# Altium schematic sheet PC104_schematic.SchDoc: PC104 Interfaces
size A2; DocumentNumber: 3; SheetNumber: 3; SheetTotal: 8
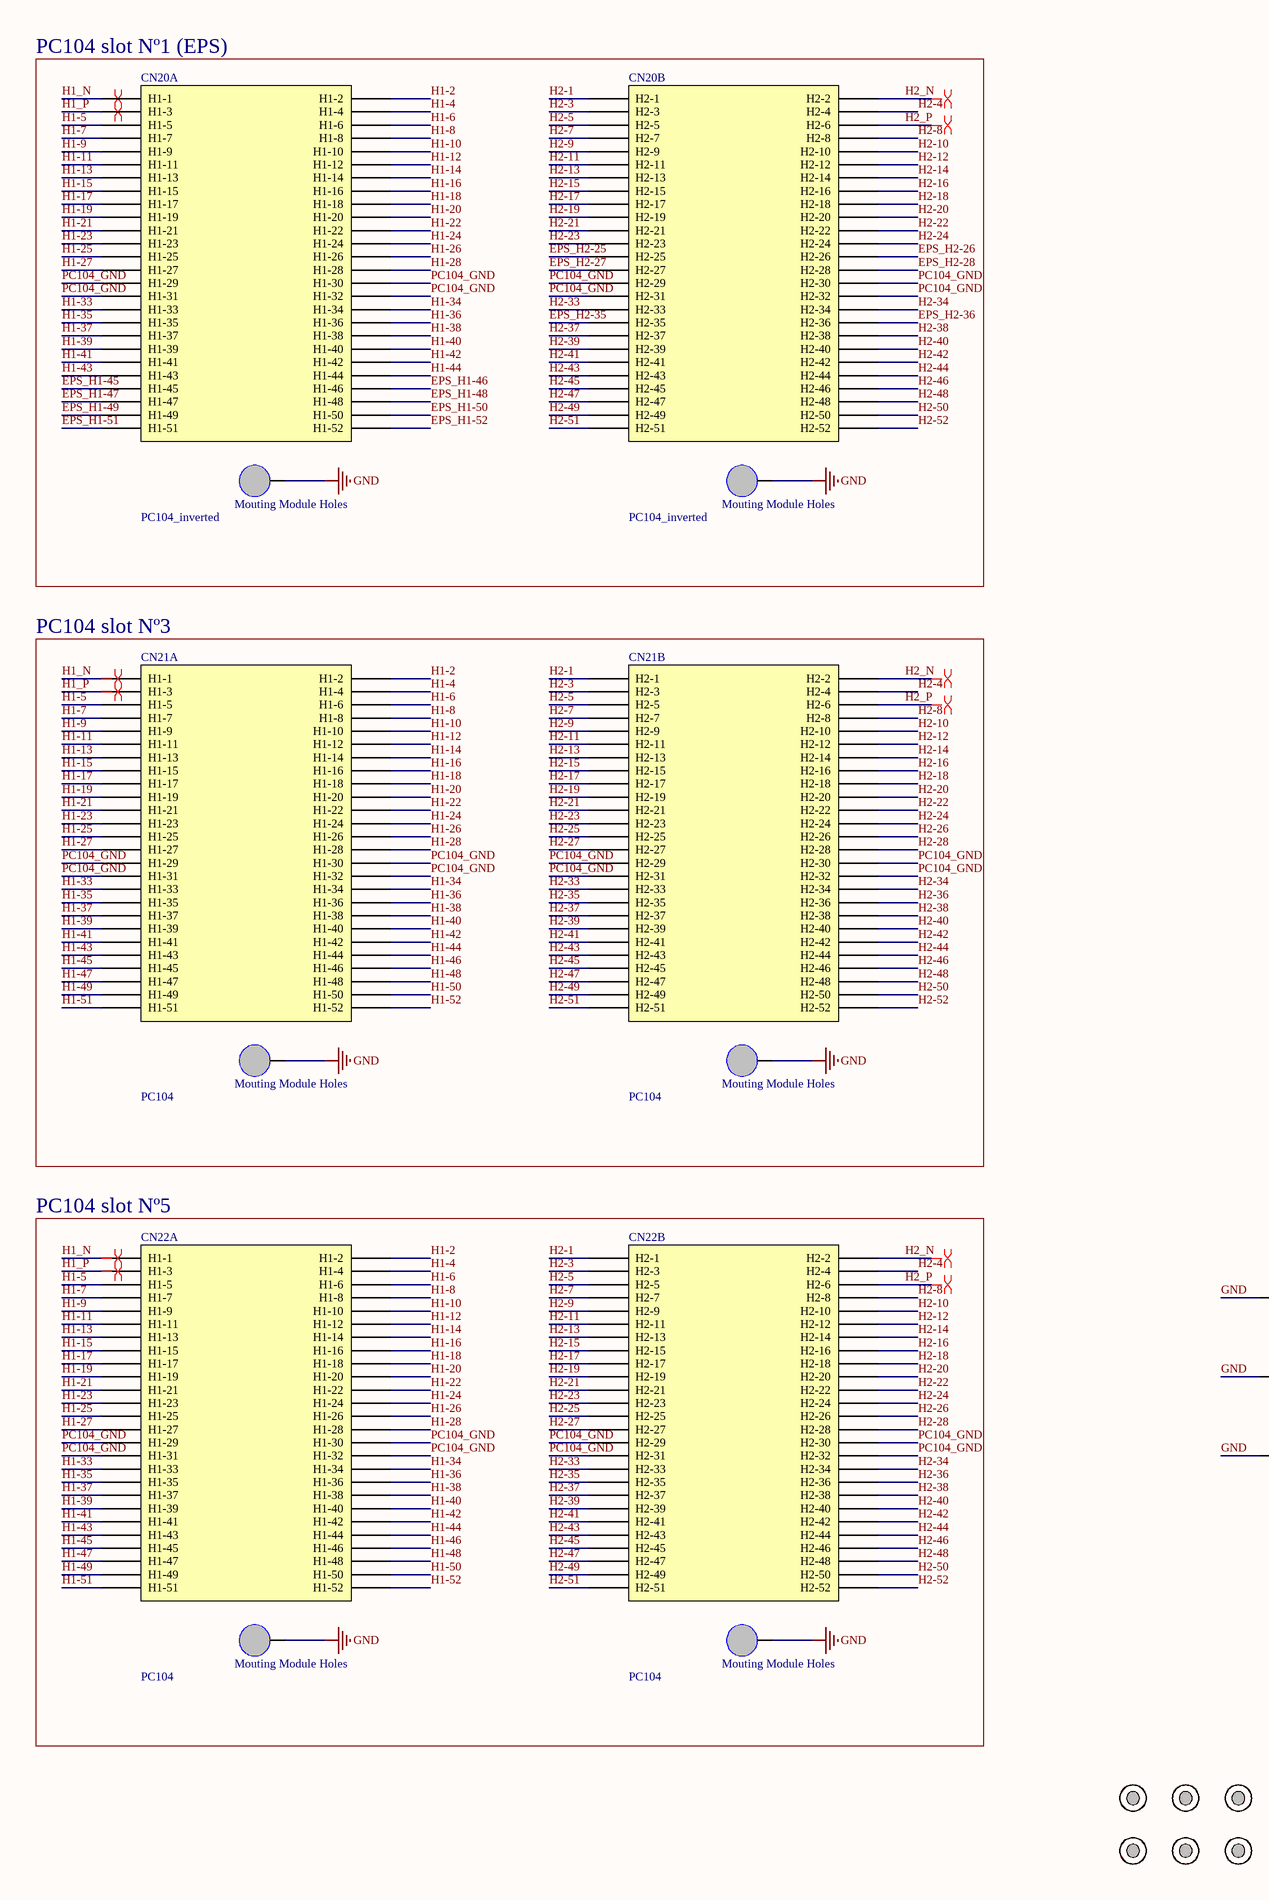
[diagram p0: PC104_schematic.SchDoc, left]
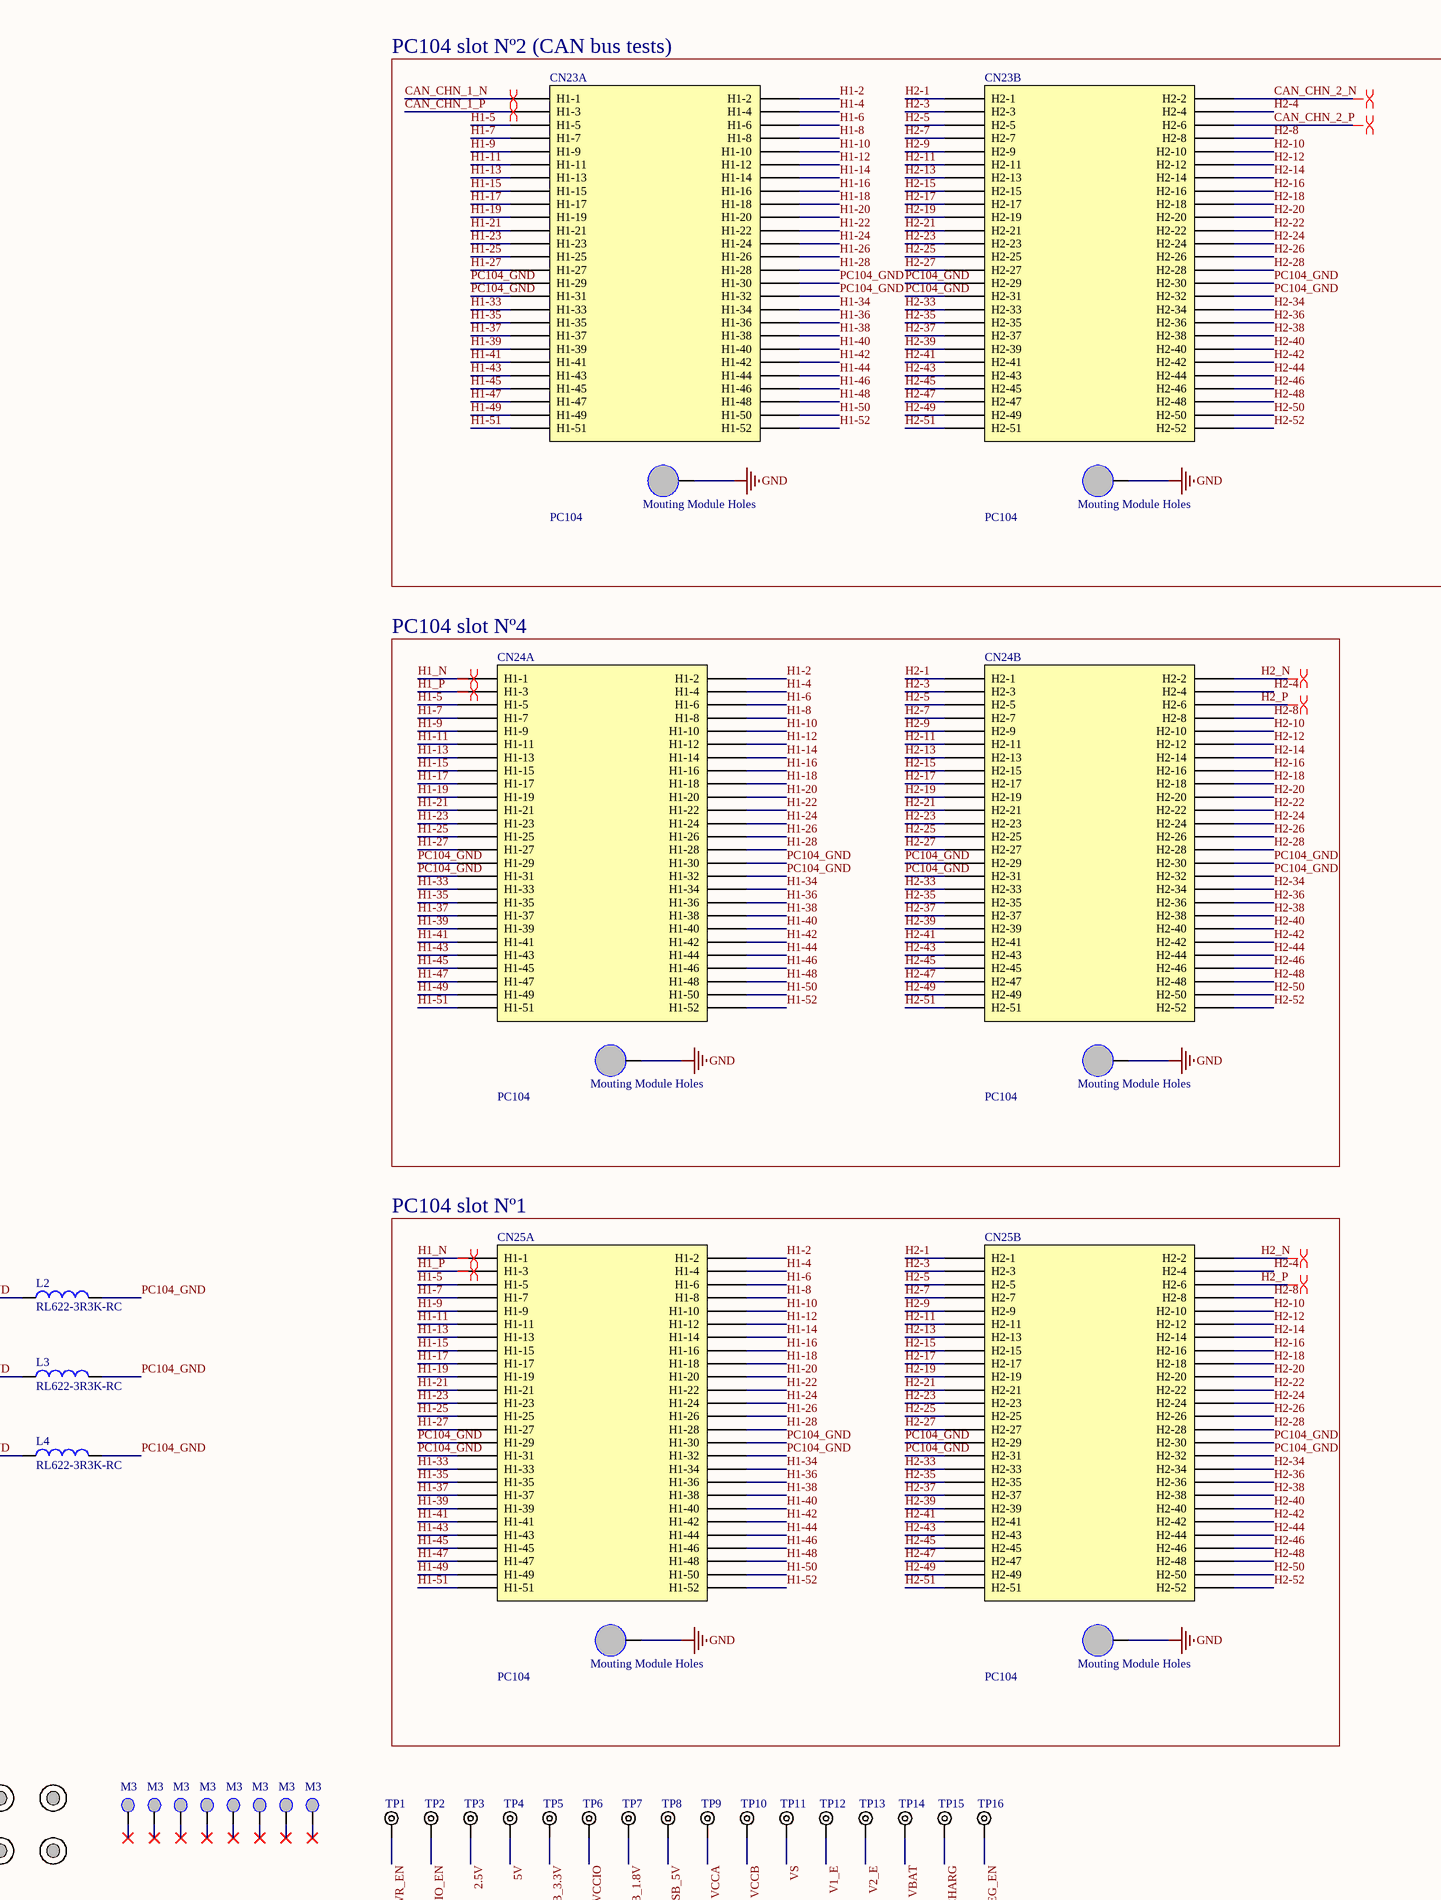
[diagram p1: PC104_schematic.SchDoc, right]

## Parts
CN20  PC104_inverted  [PC104_inverted]  (parts A,B of 2)
CN21  PC104  [PC104]  (parts A,B of 2)
CN22  PC104  [PC104]  (parts A,B of 2)
CN23  PC104  [PC104]  (parts A,B of 2)
CN24  PC104  [PC104]  (parts A,B of 2)
CN25  PC104  [PC104]  (parts A,B of 2)
FD1  Fiducial 1.3  [Fiducial 1.3mm]  (value not drawn)  (no BOM)
FD2  Fiducial 1.3  [Fiducial 1.3mm]  (value not drawn)  (no BOM)
FD3  Fiducial 1.3  [Fiducial 1.3mm]  (value not drawn)  (no BOM)
FD4  Fiducial 1.3  [Fiducial 1.3mm]  (value not drawn)  (no BOM)
FD5  Fiducial 1.3  [Fiducial 1.3mm]  (value not drawn)  (no BOM)
FD6  Fiducial 1.3  [Fiducial 1.3mm]  (value not drawn)  (no BOM)
FD7  Fiducial 1.3  [Fiducial 1.3mm]  (value not drawn)  (no BOM)
FD8  Fiducial 1.3  [Fiducial 1.3mm]  (value not drawn)  (no BOM)
L2  RL622-3R3K-RC  [RL622]
L3  RL622-3R3K-RC  [RL622]
L4  RL622-3R3K-RC  [RL622]
MEC1  M3  [M3 hole]  (no BOM)
MEC2  M3  [M3 hole]  (no BOM)
MEC3  M3  [M3 hole]  (no BOM)
MEC4  M3  [M3 hole]  (no BOM)
MEC5  M3  [M3 hole]  (no BOM)
MEC6  M3  [M3 hole]  (no BOM)
MEC7  M3  [M3 hole]  (no BOM)
MEC8  M3  [M3 hole]  (no BOM)
TP1  (no value)  [TEST POINT PTH]  (no BOM)
TP2  (no value)  [TEST POINT PTH]  (no BOM)
TP3  (no value)  [TEST POINT PTH]  (no BOM)
TP4  (no value)  [TEST POINT PTH]  (no BOM)
TP5  (no value)  [TEST POINT PTH]  (no BOM)
TP6  (no value)  [TEST POINT PTH]  (no BOM)
TP7  (no value)  [TEST POINT PTH]  (no BOM)
TP8  (no value)  [TEST POINT PTH]  (no BOM)
TP9  (no value)  [TEST POINT PTH]  (no BOM)
TP10  (no value)  [TEST POINT PTH]  (no BOM)
TP11  (no value)  [TEST POINT PTH]  (no BOM)
TP12  (no value)  [TEST POINT PTH]  (no BOM)
TP13  (no value)  [TEST POINT PTH]  (no BOM)
TP14  (no value)  [TEST POINT PTH]  (no BOM)
TP15  (no value)  [TEST POINT PTH]  (no BOM)
TP16  (no value)  [TEST POINT PTH]  (no BOM)

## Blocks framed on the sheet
PC104 slot Nº1 (EPS): CN20
PC104 slot Nº2 (CAN bus tests): CN23
PC104 slot Nº3: CN21
PC104 slot Nº4: CN24
PC104 slot Nº5: CN22
PC104 slot Nº1: CN25

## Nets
GND: CN20.0(Mouting) CN21.0(Mouting) CN22.0(Mouting) CN23.0(Mouting) CN24.0(Mouting) CN25.0(Mouting) L2.1 L3.1 L4.1
2.5V: TP3.1
5V: TP4.1
CAN_CHN_1_N: CN23.1(H1-1)
CAN_CHN_1_P: CN23.3(H1-3)
CAN_CHN_2_N: CN23.54(H2-2)
CAN_CHN_2_P: CN23.58(H2-6)
EPS_H1-45: CN20.45(H1-45)
EPS_H1-46: CN20.46(H1-46)
EPS_H1-47: CN20.47(H1-47)
EPS_H1-48: CN20.48(H1-48)
EPS_H1-49: CN20.49(H1-49)
EPS_H1-50: CN20.50(H1-50)
EPS_H1-51: CN20.51(H1-51)
EPS_H1-52: CN20.52(H1-52)
EPS_H2-25: CN20.77(H2-25)
EPS_H2-26: CN20.78(H2-26)
EPS_H2-27: CN20.79(H2-27)
EPS_H2-28: CN20.80(H2-28)
EPS_H2-35: CN20.87(H2-35)
EPS_H2-36: CN20.88(H2-36)
H1-2: CN20.2(H1-2) CN21.2(H1-2) CN22.2(H1-2) CN23.2(H1-2) CN24.2(H1-2) CN25.2(H1-2)
H1-4: CN20.4(H1-4) CN21.4(H1-4) CN22.4(H1-4) CN23.4(H1-4) CN24.4(H1-4) CN25.4(H1-4)
H1-5: CN20.5(H1-5) CN21.5(H1-5) CN22.5(H1-5) CN23.5(H1-5) CN24.5(H1-5) CN25.5(H1-5)
H1-6: CN20.6(H1-6) CN21.6(H1-6) CN22.6(H1-6) CN23.6(H1-6) CN24.6(H1-6) CN25.6(H1-6)
H1-7: CN20.7(H1-7) CN21.7(H1-7) CN22.7(H1-7) CN23.7(H1-7) CN24.7(H1-7) CN25.7(H1-7)
H1-8: CN20.8(H1-8) CN21.8(H1-8) CN22.8(H1-8) CN23.8(H1-8) CN24.8(H1-8) CN25.8(H1-8)
H1-9: CN20.9(H1-9) CN21.9(H1-9) CN22.9(H1-9) CN23.9(H1-9) CN24.9(H1-9) CN25.9(H1-9)
H1-10: CN20.10(H1-10) CN21.10(H1-10) CN22.10(H1-10) CN23.10(H1-10) CN24.10(H1-10) CN25.10(H1-10)
H1-11: CN20.11(H1-11) CN21.11(H1-11) CN22.11(H1-11) CN23.11(H1-11) CN24.11(H1-11) CN25.11(H1-11)
H1-12: CN20.12(H1-12) CN21.12(H1-12) CN22.12(H1-12) CN23.12(H1-12) CN24.12(H1-12) CN25.12(H1-12)
H1-13: CN20.13(H1-13) CN21.13(H1-13) CN22.13(H1-13) CN23.13(H1-13) CN24.13(H1-13) CN25.13(H1-13)
H1-14: CN20.14(H1-14) CN21.14(H1-14) CN22.14(H1-14) CN23.14(H1-14) CN24.14(H1-14) CN25.14(H1-14)
H1-15: CN20.15(H1-15) CN21.15(H1-15) CN22.15(H1-15) CN23.15(H1-15) CN24.15(H1-15) CN25.15(H1-15)
H1-16: CN20.16(H1-16) CN21.16(H1-16) CN22.16(H1-16) CN23.16(H1-16) CN24.16(H1-16) CN25.16(H1-16)
H1-17: CN20.17(H1-17) CN21.17(H1-17) CN22.17(H1-17) CN23.17(H1-17) CN24.17(H1-17) CN25.17(H1-17)
H1-18: CN20.18(H1-18) CN21.18(H1-18) CN22.18(H1-18) CN23.18(H1-18) CN24.18(H1-18) CN25.18(H1-18)
H1-19: CN20.19(H1-19) CN21.19(H1-19) CN22.19(H1-19) CN23.19(H1-19) CN24.19(H1-19) CN25.19(H1-19)
H1-20: CN20.20(H1-20) CN21.20(H1-20) CN22.20(H1-20) CN23.20(H1-20) CN24.20(H1-20) CN25.20(H1-20)
H1-21: CN20.21(H1-21) CN21.21(H1-21) CN22.21(H1-21) CN23.21(H1-21) CN24.21(H1-21) CN25.21(H1-21)
H1-22: CN20.22(H1-22) CN21.22(H1-22) CN22.22(H1-22) CN23.22(H1-22) CN24.22(H1-22) CN25.22(H1-22)
H1-23: CN20.23(H1-23) CN21.23(H1-23) CN22.23(H1-23) CN23.23(H1-23) CN24.23(H1-23) CN25.23(H1-23)
H1-24: CN20.24(H1-24) CN21.24(H1-24) CN22.24(H1-24) CN23.24(H1-24) CN24.24(H1-24) CN25.24(H1-24)
H1-25: CN20.25(H1-25) CN21.25(H1-25) CN22.25(H1-25) CN23.25(H1-25) CN24.25(H1-25) CN25.25(H1-25)
H1-26: CN20.26(H1-26) CN21.26(H1-26) CN22.26(H1-26) CN23.26(H1-26) CN24.26(H1-26) CN25.26(H1-26)
H1-27: CN20.27(H1-27) CN21.27(H1-27) CN22.27(H1-27) CN23.27(H1-27) CN24.27(H1-27) CN25.27(H1-27)
H1-28: CN20.28(H1-28) CN21.28(H1-28) CN22.28(H1-28) CN23.28(H1-28) CN24.28(H1-28) CN25.28(H1-28)
H1-33: CN20.33(H1-33) CN21.33(H1-33) CN22.33(H1-33) CN23.33(H1-33) CN24.33(H1-33) CN25.33(H1-33)
H1-34: CN20.34(H1-34) CN21.34(H1-34) CN22.34(H1-34) CN23.34(H1-34) CN24.34(H1-34) CN25.34(H1-34)
H1-35: CN20.35(H1-35) CN21.35(H1-35) CN22.35(H1-35) CN23.35(H1-35) CN24.35(H1-35) CN25.35(H1-35)
H1-36: CN20.36(H1-36) CN21.36(H1-36) CN22.36(H1-36) CN23.36(H1-36) CN24.36(H1-36) CN25.36(H1-36)
H1-37: CN20.37(H1-37) CN21.37(H1-37) CN22.37(H1-37) CN23.37(H1-37) CN24.37(H1-37) CN25.37(H1-37)
H1-38: CN20.38(H1-38) CN21.38(H1-38) CN22.38(H1-38) CN23.38(H1-38) CN24.38(H1-38) CN25.38(H1-38)
H1-39: CN20.39(H1-39) CN21.39(H1-39) CN22.39(H1-39) CN23.39(H1-39) CN24.39(H1-39) CN25.39(H1-39)
H1-40: CN20.40(H1-40) CN21.40(H1-40) CN22.40(H1-40) CN23.40(H1-40) CN24.40(H1-40) CN25.40(H1-40)
H1-41: CN20.41(H1-41) CN21.41(H1-41) CN22.41(H1-41) CN23.41(H1-41) CN24.41(H1-41) CN25.41(H1-41)
H1-42: CN20.42(H1-42) CN21.42(H1-42) CN22.42(H1-42) CN23.42(H1-42) CN24.42(H1-42) CN25.42(H1-42)
H1-43: CN20.43(H1-43) CN21.43(H1-43) CN22.43(H1-43) CN23.43(H1-43) CN24.43(H1-43) CN25.43(H1-43)
H1-44: CN20.44(H1-44) CN21.44(H1-44) CN22.44(H1-44) CN23.44(H1-44) CN24.44(H1-44) CN25.44(H1-44)
H1-45: CN21.45(H1-45) CN22.45(H1-45) CN23.45(H1-45) CN24.45(H1-45) CN25.45(H1-45)
H1-46: CN21.46(H1-46) CN22.46(H1-46) CN23.46(H1-46) CN24.46(H1-46) CN25.46(H1-46)
H1-47: CN21.47(H1-47) CN22.47(H1-47) CN23.47(H1-47) CN24.47(H1-47) CN25.47(H1-47)
H1-48: CN21.48(H1-48) CN22.48(H1-48) CN23.48(H1-48) CN24.48(H1-48) CN25.48(H1-48)
H1-49: CN21.49(H1-49) CN22.49(H1-49) CN23.49(H1-49) CN24.49(H1-49) CN25.49(H1-49)
H1-50: CN21.50(H1-50) CN22.50(H1-50) CN23.50(H1-50) CN24.50(H1-50) CN25.50(H1-50)
H1-51: CN21.51(H1-51) CN22.51(H1-51) CN23.51(H1-51) CN24.51(H1-51) CN25.51(H1-51)
H1-52: CN21.52(H1-52) CN22.52(H1-52) CN23.52(H1-52) CN24.52(H1-52) CN25.52(H1-52)
H1_N: CN20.1(H1-1) CN21.1(H1-1) CN22.1(H1-1) CN24.1(H1-1) CN25.1(H1-1)
H1_P: CN20.3(H1-3) CN21.3(H1-3) CN22.3(H1-3) CN24.3(H1-3) CN25.3(H1-3)
H2-1: CN20.53(H2-1) CN21.53(H2-1) CN22.53(H2-1) CN23.53(H2-1) CN24.53(H2-1) CN25.53(H2-1)
H2-3: CN20.55(H2-3) CN21.55(H2-3) CN22.55(H2-3) CN23.55(H2-3) CN24.55(H2-3) CN25.55(H2-3)
H2-4: CN20.56(H2-4) CN21.56(H2-4) CN22.56(H2-4) CN23.56(H2-4) CN24.56(H2-4) CN25.56(H2-4)
H2-5: CN20.57(H2-5) CN21.57(H2-5) CN22.57(H2-5) CN23.57(H2-5) CN24.57(H2-5) CN25.57(H2-5)
H2-7: CN20.59(H2-7) CN21.59(H2-7) CN22.59(H2-7) CN23.59(H2-7) CN24.59(H2-7) CN25.59(H2-7)
H2-8: CN20.60(H2-8) CN21.60(H2-8) CN22.60(H2-8) CN23.60(H2-8) CN24.60(H2-8) CN25.60(H2-8)
H2-9: CN20.61(H2-9) CN21.61(H2-9) CN22.61(H2-9) CN23.61(H2-9) CN24.61(H2-9) CN25.61(H2-9)
H2-10: CN20.62(H2-10) CN21.62(H2-10) CN22.62(H2-10) CN23.62(H2-10) CN24.62(H2-10) CN25.62(H2-10)
H2-11: CN20.63(H2-11) CN21.63(H2-11) CN22.63(H2-11) CN23.63(H2-11) CN24.63(H2-11) CN25.63(H2-11)
H2-12: CN20.64(H2-12) CN21.64(H2-12) CN22.64(H2-12) CN23.64(H2-12) CN24.64(H2-12) CN25.64(H2-12)
H2-13: CN20.65(H2-13) CN21.65(H2-13) CN22.65(H2-13) CN23.65(H2-13) CN24.65(H2-13) CN25.65(H2-13)
H2-14: CN20.66(H2-14) CN21.66(H2-14) CN22.66(H2-14) CN23.66(H2-14) CN24.66(H2-14) CN25.66(H2-14)
H2-15: CN20.67(H2-15) CN21.67(H2-15) CN22.67(H2-15) CN23.67(H2-15) CN24.67(H2-15) CN25.67(H2-15)
H2-16: CN20.68(H2-16) CN21.68(H2-16) CN22.68(H2-16) CN23.68(H2-16) CN24.68(H2-16) CN25.68(H2-16)
H2-17: CN20.69(H2-17) CN21.69(H2-17) CN22.69(H2-17) CN23.69(H2-17) CN24.69(H2-17) CN25.69(H2-17)
H2-18: CN20.70(H2-18) CN21.70(H2-18) CN22.70(H2-18) CN23.70(H2-18) CN24.70(H2-18) CN25.70(H2-18)
H2-19: CN20.71(H2-19) CN21.71(H2-19) CN22.71(H2-19) CN23.71(H2-19) CN24.71(H2-19) CN25.71(H2-19)
H2-20: CN20.72(H2-20) CN21.72(H2-20) CN22.72(H2-20) CN23.72(H2-20) CN24.72(H2-20) CN25.72(H2-20)
H2-21: CN20.73(H2-21) CN21.73(H2-21) CN22.73(H2-21) CN23.73(H2-21) CN24.73(H2-21) CN25.73(H2-21)
H2-22: CN20.74(H2-22) CN21.74(H2-22) CN22.74(H2-22) CN23.74(H2-22) CN24.74(H2-22) CN25.74(H2-22)
H2-23: CN20.75(H2-23) CN21.75(H2-23) CN22.75(H2-23) CN23.75(H2-23) CN24.75(H2-23) CN25.75(H2-23)
H2-24: CN20.76(H2-24) CN21.76(H2-24) CN22.76(H2-24) CN23.76(H2-24) CN24.76(H2-24) CN25.76(H2-24)
H2-25: CN21.77(H2-25) CN22.77(H2-25) CN23.77(H2-25) CN24.77(H2-25) CN25.77(H2-25)
H2-26: CN21.78(H2-26) CN22.78(H2-26) CN23.78(H2-26) CN24.78(H2-26) CN25.78(H2-26)
H2-27: CN21.79(H2-27) CN22.79(H2-27) CN23.79(H2-27) CN24.79(H2-27) CN25.79(H2-27)
H2-28: CN21.80(H2-28) CN22.80(H2-28) CN23.80(H2-28) CN24.80(H2-28) CN25.80(H2-28)
H2-33: CN20.85(H2-33) CN21.85(H2-33) CN22.85(H2-33) CN23.85(H2-33) CN24.85(H2-33) CN25.85(H2-33)
H2-34: CN20.86(H2-34) CN21.86(H2-34) CN22.86(H2-34) CN23.86(H2-34) CN24.86(H2-34) CN25.86(H2-34)
H2-35: CN21.87(H2-35) CN22.87(H2-35) CN23.87(H2-35) CN24.87(H2-35) CN25.87(H2-35)
H2-36: CN21.88(H2-36) CN22.88(H2-36) CN23.88(H2-36) CN24.88(H2-36) CN25.88(H2-36)
H2-37: CN20.89(H2-37) CN21.89(H2-37) CN22.89(H2-37) CN23.89(H2-37) CN24.89(H2-37) CN25.89(H2-37)
H2-38: CN20.90(H2-38) CN21.90(H2-38) CN22.90(H2-38) CN23.90(H2-38) CN24.90(H2-38) CN25.90(H2-38)
H2-39: CN20.91(H2-39) CN21.91(H2-39) CN22.91(H2-39) CN23.91(H2-39) CN24.91(H2-39) CN25.91(H2-39)
H2-40: CN20.92(H2-40) CN21.92(H2-40) CN22.92(H2-40) CN23.92(H2-40) CN24.92(H2-40) CN25.92(H2-40)
H2-41: CN20.93(H2-41) CN21.93(H2-41) CN22.93(H2-41) CN23.93(H2-41) CN24.93(H2-41) CN25.93(H2-41)
H2-42: CN20.94(H2-42) CN21.94(H2-42) CN22.94(H2-42) CN23.94(H2-42) CN24.94(H2-42) CN25.94(H2-42)
H2-43: CN20.95(H2-43) CN21.95(H2-43) CN22.95(H2-43) CN23.95(H2-43) CN24.95(H2-43) CN25.95(H2-43)
H2-44: CN20.96(H2-44) CN21.96(H2-44) CN22.96(H2-44) CN23.96(H2-44) CN24.96(H2-44) CN25.96(H2-44)
H2-45: CN20.97(H2-45) CN21.97(H2-45) CN22.97(H2-45) CN23.97(H2-45) CN24.97(H2-45) CN25.97(H2-45)
H2-46: CN20.98(H2-46) CN21.98(H2-46) CN22.98(H2-46) CN23.98(H2-46) CN24.98(H2-46) CN25.98(H2-46)
H2-47: CN20.99(H2-47) CN21.99(H2-47) CN22.99(H2-47) CN23.99(H2-47) CN24.99(H2-47) CN25.99(H2-47)
H2-48: CN20.100(H2-48) CN21.100(H2-48) CN22.100(H2-48) CN23.100(H2-48) CN24.100(H2-48) CN25.100(H2-48)
H2-49: CN20.101(H2-49) CN21.101(H2-49) CN22.101(H2-49) CN23.101(H2-49) CN24.101(H2-49) CN25.101(H2-49)
H2-50: CN20.102(H2-50) CN21.102(H2-50) CN22.102(H2-50) CN23.102(H2-50) CN24.102(H2-50) CN25.102(H2-50)
H2-51: CN20.103(H2-51) CN21.103(H2-51) CN22.103(H2-51) CN23.103(H2-51) CN24.103(H2-51) CN25.103(H2-51)
H2-52: CN20.104(H2-52) CN21.104(H2-52) CN22.104(H2-52) CN23.104(H2-52) CN24.104(H2-52) CN25.104(H2-52)
H2_N: CN20.54(H2-2) CN21.54(H2-2) CN22.54(H2-2) CN24.54(H2-2) CN25.54(H2-2)
H2_P: CN20.58(H2-6) CN21.58(H2-6) CN22.58(H2-6) CN24.58(H2-6) CN25.58(H2-6)
PC104_GND: CN20.29(H1-29) CN20.30(H1-30) CN20.31(H1-31) CN20.32(H1-32) CN20.81(H2-29) CN20.82(H2-30) CN20.83(H2-31) CN20.84(H2-32) CN21.29(H1-29) CN21.30(H1-30) CN21.31(H1-31) CN21.32(H1-32) CN21.81(H2-29) CN21.82(H2-30) CN21.83(H2-31) CN21.84(H2-32) CN22.29(H1-29) CN22.30(H1-30) CN22.31(H1-31) CN22.32(H1-32) CN22.81(H2-29) CN22.82(H2-30) CN22.83(H2-31) CN22.84(H2-32) CN23.29(H1-29) CN23.30(H1-30) CN23.31(H1-31) CN23.32(H1-32) CN23.81(H2-29) CN23.82(H2-30) CN23.83(H2-31) CN23.84(H2-32) CN24.29(H1-29) CN24.30(H1-30) CN24.31(H1-31) CN24.32(H1-32) CN24.81(H2-29) CN24.82(H2-30) CN24.83(H2-31) CN24.84(H2-32) CN25.29(H1-29) CN25.30(H1-30) CN25.31(H1-31) CN25.32(H1-32) CN25.81(H2-29) CN25.82(H2-30) CN25.83(H2-31) CN25.84(H2-32) L2.2 L3.2 L4.2
PWR_EN: TP1.1
REG_EN: TP16.1
USB_1.8V: TP7.1
USB_3.3V: TP5.1
USB_5V: TP8.1
V1_E: TP12.1
V2_E: TP13.1
VBAT: TP14.1
VCCA: TP9.1
VCCB: TP10.1
VCCIO: TP6.1
VCCIO_EN: TP2.1
VCHARG: TP15.1
VS: TP11.1

Not connected (* = marked no-connect by the designer): MEC1 0*; MEC2 0*; MEC3 0*; MEC4 0*; MEC5 0*; MEC6 0*; MEC7 0*; MEC8 0*

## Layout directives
differential pair: CAN_CHN_1_N, CAN_CHN_1_P, CAN_CHN_2_N, CAN_CHN_2_P, H1_N, H1_P, H2_N, H2_P

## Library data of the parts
CN20 = PC104_inverted: Manufacturer Part Number: TSW-126-07-G-D
CN21-CN25 = PC104: Manufacturer Part Number: SSW-126-01-G-D
FD1-FD8 = Fiducial 1.3: Fiducial 1.3mm
L2-L4 = RL622-3R3K-RC: 3.3ÂµH Unshielded Wirewound Inductor 5.5A 25mOhm Max Radial, Vertical Cylinder; MF: Bourns
MEC1-MEC8 = M3 hole
TP1-TP16 = Test Point PTH: TEST POINT PAD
